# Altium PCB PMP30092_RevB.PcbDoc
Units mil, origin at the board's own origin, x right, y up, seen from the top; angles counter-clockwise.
Board outline 7537.5 x 2575 mil, 2 copper layers (Top Layer, Bottom Layer), stack 62 mil thick; 65 components, 37 nets, 152 pads, 61 vias.
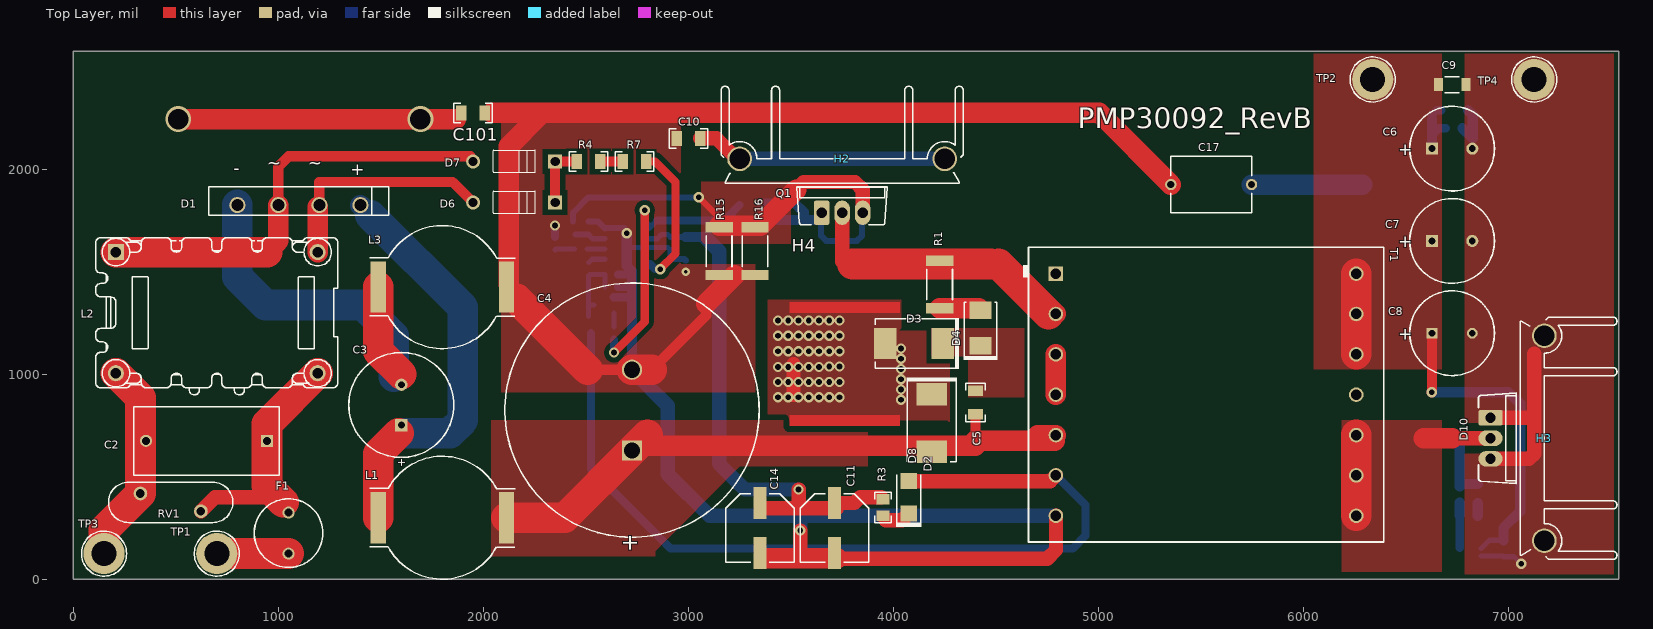
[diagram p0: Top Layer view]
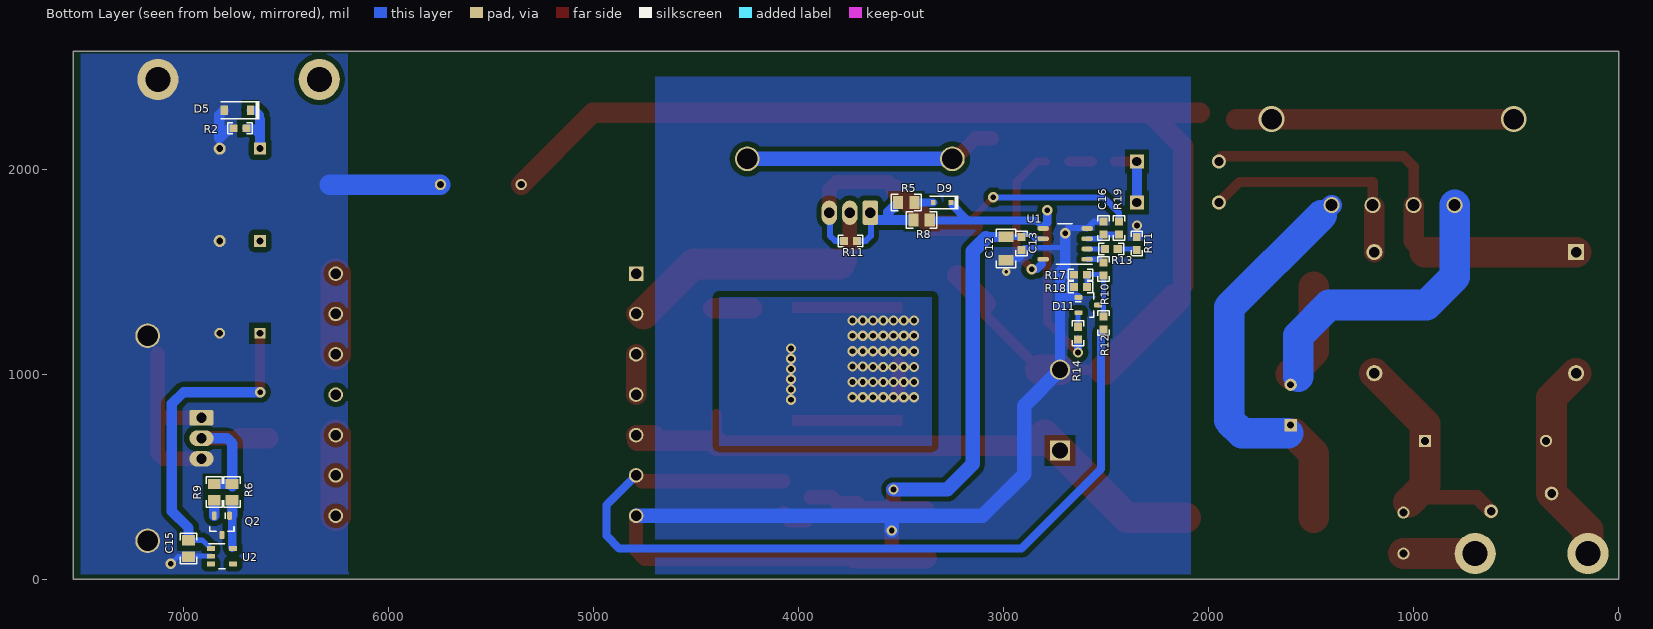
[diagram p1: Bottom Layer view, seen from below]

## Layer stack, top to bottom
Top Solder: solder mask 0.4, Solder Resist, Dk 3.5
Top Layer: signal copper 1.4
Dielectric1: core 59.2, FR-4, Dk 4.8
Bottom Layer: signal copper 1.4
Bottom Solder: solder mask 0.4, Solder Resist, Dk 3.5

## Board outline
0,0 7537.5,0 7537.5,2575 0,2575

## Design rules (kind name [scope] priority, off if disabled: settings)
AcuteAngle [All] p1: minimum=4.50000000000000E+0001 checktracksonly=FALSE
AssemblyTestPointUsage [All] p1: valid=2
Clearance Clearance_1 [InNet('NetD2_1') vs InNet('NetC4_1')] p1: gap=30
Clearance Clearance_Keepouts [((IsTrack Or IsArc) And Not InPoly) And IsFree and IsKeepOut vs ((IsTrack Or IsArc) And Not InPoly) And IsFree and IsKeepOut] p2: gap=0
Clearance Clearance_BoardEdge_MountingHoles [OnCopper and InComponentClass('Mounting Holes') vs IsKeepOut] p3: gap=20
Clearance Clearance_BoardEdge_Poly [OnCopper and InPoly vs IsKeepOut] p4: gap=25
Clearance Clearance_BoardEdge [OnCopper and Not InComponentClass('Logo') and not InComponentClass('FiducialMark') and not InRegion(1000,500,4000,800) and Not IsKeepout vs IsKeepOut] p5: gap=20
Clearance Clearance_Poly [InPolygon] p6: gap=25
Clearance [All] p7: gap=7.87
ComponentClearance ComponentClearance_MountingHoles_FiducialMarks [InComponentClass('Mounting Holes') vs InComponentClass('FiducialMark')] p1: gap=50 collisioncheckmode=3 verticalgap=10 showdistances=FALSE
ComponentClearance ComponentClearance_Shunt [InComponentClass('Header') vs InComponentClass('Shunt')] p2: gap=0 collisioncheckmode=3 verticalgap=0 showdistances=FALSE
ComponentClearance ComponentClearance_Logo [InComponentClass('Logo')] p3: gap=50 collisioncheckmode=3 verticalgap=10 showdistances=FALSE
ComponentClearance ComponentClearance_ScrewToNut [(HasFootprint('NY PMS 440 0025 PH')) vs (HasFootprint('Keystone_1902C'))] p4: gap=5 collisioncheckmode=3 verticalgap=10 showdistances=FALSE
ComponentClearance ComponentClearance_MountingHoles [InComponentClass('Mounting Holes')] p5: gap=250 collisioncheckmode=3 verticalgap=100000 showdistances=FALSE
ComponentClearance ComponentClearance_SmallPassives [HasFootprint('0201*') or HasFootprint('0402*') or HasFootprint('0508') or HasFootprint('0603*') or HasFootprint('0612') or HasFootprint('0805*') or HasFootprint('0815*') or HasFootprint('0830*') or HasFootprint('1206*') or HasFootprint('1210*') or HasFootprint('1808*') or HasFootprint('1812*') or HasFootprint('1825*') or HasFootprint('2010*') or HasFootprint('2220*') or HasFootprint('2225*') or HasFootprint('2512*') or HasFootprint('2728*') or HasFootprint('3518*') vs HasFootprint('0201*') or HasFootprint('0402*') or HasFootprint('0508') or HasFootprint('0603*') or HasFootprint('0612') or HasFootprint('0805*') or HasFootprint('0815*') or HasFootprint('0830*') or HasFootprint('1206*') or HasFootprint('1210*') or HasFootprint('1808*') or HasFootprint('1812*') or HasFootprint('1825*') or HasFootprint('2010*') or HasFootprint('2220*') or HasFootprint('2225*') or HasFootprint('2512*') or HasFootprint('2728*') or HasFootprint('3518*')] p6: gap=20 collisioncheckmode=3 verticalgap=10 showdistances=FALSE
ComponentClearance ComponentClearance_THtoSMT [IsThruComponent vs IsSMTComponent] p7: gap=20 collisioncheckmode=3 verticalgap=30 showdistances=FALSE
ComponentClearance ComponentClearance_THtoTH [IsThruComponent vs IsThruComponent] p8: gap=10 collisioncheckmode=3 verticalgap=30 showdistances=FALSE
ComponentClearance [All] p9: gap=10 collisioncheckmode=3 verticalgap=10 showdistances=FALSE
DiffPairsRouting [All] p1: maxlimit=100 minlimit=10 mostfreqgap=10 toplayer_minwidth=15 toplayer_maxwidth=15 toplayer_prefwidth=15 bottomlayer_minwidth=15 bottomlayer_maxwidth=15 bottomlayer_prefwidth=15 maxuncoupledlength=1000
FabricationTestPointUsage TestPointUsage [All] p1: valid=2 allowmultiple=FALSE
FabricationTestpoint Testpoint [All] p1: side=3 testpointundercomponent=TRUE minsize=40 maxsize=100 preferedsize=60 minholesize=0 maxholesize=40 preferedholesize=32 testpointgrid=1 allowsidetop=TRUE allowsidebottom=TRUE usegrid=TRUE gridtolerance=0.01
FanoutControl Fanout_LCC [IsLCC] p1: bgadir=Out bgaviamode=Centered fanoutstyle=Auto fanoutdirection=Alternating viagrid=1 // Fanout_LCC (Default Rule)
FanoutControl Fanout_BGA [IsBGA] p2: bgadir=Out bgaviamode=Centered fanoutstyle=Auto fanoutdirection=Alternating viagrid=1 // Fanout_BGA (Default Rule)
FanoutControl Fanout_Default [All] p4: bgadir=Out bgaviamode=Centered fanoutstyle=Auto fanoutdirection=Alternating viagrid=1 // Fanout_Default (Default Rule)
FanoutControl Fanout_Small [(CompPinCount < 5)] p5: bgadir=Out bgaviamode=Centered fanoutstyle=Auto fanoutdirection=OutThenIn viagrid=1 // Fanout_Small (Default Rule)
Height [All] p1: minheight=0 maxheight=2000 prefheight=500
HoleSize [All] p1: absolutevalues=TRUE maxlimit=251 minlimit=8 maxpercent=80.000 minpercent=20.000
MinimumAnnularRing MinimumAnnularRing_ThermalPadVias [IsVia and InAnyComponent] p1: minimumring=5.91
MinimumAnnularRing [All] p2: minimumring=9
MinimumSolderMaskSliver MinimumSolderMaskSliver_Logo [InComponentClass('Logo') vs InComponentClass('Logo')] p1: minsoldermaskwidth=0.7
MinimumSolderMaskSliver [All] p2: minsoldermaskwidth=3.94
PlaneConnect [All] p1: planeconnectstyle=Relief reliefexpansion=10 reliefentries=4 reliefconductorwidth=10 reliefairgap=10
PolygonConnect [All] p1: connectstyle=Direct reliefconductorwidth=10 reliefentries=4 polygonreliefangle="90 Angle" airgapwidth=10
RoutingVias ThermalPadVias [IsVia and InAnyComponent] p1: holewidth=7.87 width=19.68 viastyle="Through Hole" minholewidth=7.87 minwidth=19.68 maxholewidth=12.99 maxwidth=23.62
RoutingVias [All] p2: holewidth=16 width=34 viastyle="Through Hole" minholewidth=7.87 minwidth=26 maxholewidth=40 maxwidth=65
SilkToBoardRegionClearance [Not ((IsComment or IsDesignator) And (Hide <> 'False')) and not InRegion(1000,500,4000,800)] p1:
SilkToSilkClearance SilkToSilkClearance_Pb-FreeLogo [(HasFootprint('Pb-Free_Overlay_Medium') OR HasFootprint('Pb-Free_Overlay_Small')) vs (HasFootprint('Pb-Free_Overlay_Medium') OR HasFootprint('Pb-Free_Overlay_Small'))] p1: silktosilkclearance=0
SilkToSilkClearance [All] p2: silktosilkclearance=4
SilkToSolderMaskClearance SilkToComonentPadClearance [IsPad and InAnycomponent] p1: minsilkscreentomaskgap=5 clearancetoexposedcopper=TRUE
SilkToSolderMaskClearance "Silk to Solder Mask Opening" [All] p2: minsilkscreentomaskgap=4 clearancetoexposedcopper=FALSE
SolderMaskExpansion [All] p1: expansion=1.97
Width [All] p1: maxlimit=150 minlimit=6 preferedwidth=10 minimp=50.000000 maximp=50.000000 favimp=50.000000 checkconnectedcopper=TRUE
14 further rules are at their usual default settings.

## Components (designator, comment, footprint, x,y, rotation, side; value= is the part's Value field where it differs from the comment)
C2 "B32922C3334M" B32922_14.5mm 650,675 r180 top
C3 "UCY2G180MPD" CY_1250x2000 1600,850 r90 top
C4 "LGW2G271MELB35" LGW_3000x3500 2725,825 r90 top
C5 "12062A100JAT2A" 1206 4400,862.5 r90 top
C6 "UHW1V681MPD6" HW_1000x2000 6725,2100 r0 top
C7 "UHW1V681MPD6" HW_1000x2000 6725,1650 r0 top
C8 "UHW1V471MPD" HW_1000x1600 6725,1200 r0 top
C9 "C3216X7R1H105K160AB" 1206_180 6725,2412.5 r0 top
C10 "GRM31BR72J102KW01L" 1206 3000,2150 r180 top
C11 "EEE-FC1V330P" SM_RADIAL_E 3712.5,250 r270 top
C12 "C1206C105K3RACTU" 1206 2987.5,1612.5 r270 bottom
C13 "06035C104KAT2A" 0603 2912.5,1637.5 r270 bottom
C14 "Used in BOM report" SM_RADIAL_E 3350,250 r270 top
C15 "08055C104KAT2A" 0805_HV 6975,150 r270 bottom
C16 "06035A101FAT2A" 0603 2512.5,1712.5 r90 bottom
C17 "DE1E3KX332MN4AP01F" KX_1000x700 5550,1925 r180 top
C101 "GRM31BR72J102KW01L" 1206 1950,2275 r180 top
D1 "GBU606" GBU 1100,1825 r180 top
D2 "SMCJ85A" SMC 4187.5,762.5 r270 top
D3 "SMCJ100A" SMC 4100,1150 r180 top
D4 "MURS160T3G" SMB 4425,1225 r90 top
D5 "MMSZ5255B-7-F" SOD-123 6737.5,2287.5 r0 bottom
D6 "1N4007" DO-41 2150,1837.5 r180 top
D7 "1N4007" DO-41 2150,2037.5 r180 top
D8 "ES1B-13-F" SMA 4075,400 r90 top
D9 "BAS316,115" sod-323 3300,1837.5 r0 bottom
D10 "MBR20H150CTG" TO-220AB 6912.5,687.5 r270 top
D11 "BAV70-E3-08" SOT-23 2587.5,1337.5 r180 bottom
F1 "37213150001" FUSE_372 1050,225 r270 top
H2 "V6560X" ASMN_V6560X 3750,2050 r0 top
H3 "V6560X" ASMN_V6560X 7175,687.5 r270 top
H4 "573300D00010G" HEATSINK_573300D00010G 3762.5,1050 r90 top
L1 "DO5040H-473MLB" DO5040H 1800,300 r0 top
L2 "744825510" WE-CMB_XL 700,1300 r0 top
L3 "DO5040H-473MLB" DO5040H 1800,1425 r0 top
Q1 "IPP60R385CP" TO-220AB 3750,1787.5 r0 top
Q2 "TBD" SOT-23 6812.5,262.5 r270 bottom
R1 "CRCW25120000Z0EG" 2512 4225,1437.5 r90 top
R2 "RC0603FR-0720KL" 0603 6725,2200 r180 bottom
R3 "CRCW080510R0FKEA" 0805_HV 3950,350 r90 top
R4 "CRCW1206100KFKEA" 1206 2512.5,2037.5 r180 top
R5 "CRCW08050000Z0EA" 0805_HV 3475,1837.5 r0 bottom
R6 "CRCW08052K15FKEA" 0805_HV 6762.5,425 r270 bottom
R7 "CRCW1206100KFKEA" 1206 2737.5,2037.5 r180 top
R8 "CRCW080510R0FKEA" 0805_HV 3400,1751.57 r0 bottom
R9 "CRCW0805100RFKEA" 0805_HV 6850,425 r270 bottom
R10 "CRCW0603100RFKEA" 0603 2512.5,1512.5 r90 bottom
R11 "CRCW0603100KFKEA" 0603 3746.95,1650 r180 bottom
R12 "CRCW060321K5FKEA" 0603 2512.5,1250 r270 bottom
R13 "CRCW06030000Z0EA" 0603 2475,1610.81 r0 bottom
R14 "CRCW06033K92FKEA" 0603 2637.5,1200 r270 bottom
R15 "RLP73K3AR16FTDF" 2512 3150,1600 r90 top
R16 "Used in BOM report" 2512 3325,1600 r90 top
R17 "CRCW060337K4FKEA" 0603 2625,1485.81 r180 bottom
R18 "Used in BOM report" 0603 2625,1425 r180 bottom
R19 "CRCW06031K00FKEA" 0603 2437.5,1712.5 r270 bottom
RT1 "NCP18WM474J03RB" 0603 2350,1637.5 r270 bottom
RV1 "B72214S0271K101" VAR_B72214S0271 475,375 r0 top
T1 "750316326" Wurth_750316326 5525,900 r0 top
TP1 "Suggest using a net name here" Keystone1503-2 700,125 r0 top
TP2 "Suggest using a net name here" Keystone1503-2 6337.5,2437.5 r0 top
TP3 "Suggest using a net name here" Keystone1503-2 150,125 r0 top
TP4 "Suggest using a net name here" Keystone1503-2 7125,2437.5 r0 top
U1 "UCC28633DR" D0007A_N 2700,1635.81 r0 bottom
U2 "UCC24650DBVR" DBV0005A_N 6812.5,112.5 r180 bottom

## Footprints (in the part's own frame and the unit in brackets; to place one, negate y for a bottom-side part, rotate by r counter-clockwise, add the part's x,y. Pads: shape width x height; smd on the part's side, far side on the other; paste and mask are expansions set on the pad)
0603 [mm] "0603 from SM-752 data"
  rect 1x0.95 smd: 1(-0.8,0) 2(0.8,0)
  silkscreen extent -1.52,-0.69 1.52,0.69, body extent -0.87,-0.47 0.87,0.47, height 1
0805_HV [mil] "0805 with 30mil clearance between pads"
  rect 50x63 smd: 1(-40,0) 2(40,0)
  silkscreen extent -74,-40 74,40, body extent -43,-29 43,29, height 57
1206 [mm] "1206 from SM-752 data"
  rect 1.3x1.85 smd: 1(-1.45,0) 2(1.45,0)
  silkscreen extent -2.4,-1.21 2.4,1.21, body extent -1.7,-0.9 1.7,0.9, height 1.35
1206_180 [mm] "1206_180"
  rect 1.1x1.6 smd: 1(-1.7,0) 2(1.7,0)
  silkscreen extent -0.9,-1 0.9,1, body extent -1.75,-0.95 1.75,0.95, height 1.8
2512 [mm] "Chip Resistor, Body 6.3x3.2mm, IPC Medium Density"
  rect 1.3x3.4 smd: 1(-2.95,0) 2(2.95,0)
  silkscreen extent -1.9,-1.6 1.9,1.6, body extent -3.22,-1.67 3.22,1.67, height 0.71
ASMN_V6560X [mm] "TH, 2-Leads, Body 29x12mm, Pitch 25.4mm"
  round 3.05 hole 2.55: 1(-12.7,0) 2(12.7,0)
  silkscreen extent -15,-3 15,9, body extent -15,-3 15,9, height 37.5
B32922_14.5mm [mm] "Epcos film capacitors, 15mm spacing"
  rect 1.5x1.5 hole 1: 1(-7.5,0)
  round 1.5 hole 1: 2(7.5,0)
  silkscreen extent -9,-4.25 9,4.25, body extent -9,-4.25 9,4.25, height 14.5
CY_1250x2000 [mil] "Nichicon"
  rect 60x60 hole 33.46: 1(-98.43,0)
  round 60 hole 33.46: 2(98.43,0)
  silkscreen extent -256,-256 256,256, body extent -255,-255 255,256, height 847
D0007A_N [mm] "SOIC, 7-Leads, Body 4.9x3.9mm, Pitch 1.27mm, IPC Medium Density"
  oval 1.45x0.6 smd: 1(-2.725,1.905) 2(-2.725,0.635) 3(-2.725,-0.635) 4(-2.725,-1.905) 5(2.725,-1.905) 6(2.725,-0.635) 8(2.725,1.905)
  silkscreen extent -3.32,-2.5 1.1,2.52, body extent -3.01,-2.45 3.01,2.45, height 1.75
DBV0005A_N [mm] "SOT23, 5-Leads, Body 2.9x1.6mm, Pitch 0.95mm, Lead Span 2.8mm, IPC Medium Density"
  rrect17% 1x0.6 smd: 1(-1.375,0.95) 2(-1.375,0) 3(-1.375,-0.95) 4(1.375,-0.95) 5(1.375,0.95)
  silkscreen extent -1.63,-1.55 0.38,1.55, body extent -1.42,-1.46 1.42,1.46, height 1.09
DO5040H [mm] "Coilcraft recommended land pattern.  Document 479-2, rev 10/14/08"
  rect 1.9x6.35 smd: 1(-7.95,0) 2(7.95,0)
  silkscreen extent -9.01,-7.62 9,7.62, body extent -9.26,-7.55 9.28,7.55, height 12
DO-41 [mm] "diode"
  rect 1.75x1.75 hole 1.15: 1(-5.08,0)
  round 1.75 hole 1.15: 2(5.08,0)
  silkscreen extent -2.62,-1.37 2.59,1.35, body extent -5.51,-1.36 5.51,1.36, height 2.72
FUSE_372 [mm] "LITTELFUSE"
  round 1.5 hole 1: 1(-2.54,0) 2(2.54,0)
  silkscreen extent -4.25,-4.25 4.25,4.25, body extent -4.25,-4.25 4.25,4.25, height 8
GBU [mm] "Comchip / Diodes Inc diode bridge"
  round 2 hole 1.5: 1(-7.62,0) 2(-2.54,0) 3(2.54,0) 4(7.62,0)
  silkscreen extent -11.15,-2.28 11.15,1.28, body extent -11.15,-2.28 11.15,1.28, height 21.55
HEATSINK_573300D00010G [mil] "Aavid"
  Top Layer region: 248.03,-269.69 303.15,-269.69 303.15,269.68 248.03,269.68
  Top Layer region: -248.03,269.68 -303.15,269.68 -303.15,-269.69 -248.03,-269.69
  body extent -515,-250 515,250, height 400
HW_1000x1600 [mm] "TH, 2-Leads, Dia 10mm, Pin Spacing 5mm"
  rect 1.35x1.35 hole 0.85: 1(-2.5,0)
  round 1.35 hole 0.85: 2(2.5,0)
  silkscreen extent -5.25,-5.25 5.25,5.25, body extent -5.25,-5.25 5.26,5.25, height 17.51
HW_1000x2000 [mm] "TH, 2-Leads, 10.5x22mm, Pin Spacing 5mm"
  rrect7% 1.5x1.5 hole 0.85: 1(-2.5,0)
  round 1.5 hole 0.85: 2(2.5,0)
  silkscreen extent -5.25,-5.25 5.25,5.25, body extent -5.21,-5.24 5.24,5.24, height 22.01
Keystone1503-2 [mm] "Double Turret"
  round 5.1 hole 3.1: 1(0,0)
  silkscreen extent -2.79,-2.79 2.79,2.79, body extent -2.4,-2.4 2.38,2.4, height 9.22
KX_1000x700 [mm] "TH, 2-Leads, Dia 10mm, Lead Spacing 10mm"
  round 1.4 hole 0.9: 1(-5,0) 2(5,0)
  silkscreen extent -5,-3.5 5,3.5, body extent -5.32,-3.5 5.33,3.5, height 12.99
LGW_3000x3500 [mm] "TH, 2-Leads, Dia 30mm, Pin Spacing 10mm"
  rect 2.5x2.5 hole 2: 1(-5,0)
  round 2.5 hole 2: 2(5,0)
  silkscreen extent -15.75,-15.75 15.75,15.75, body extent -15.75,-15.75 15.76,15.75, height 37.01
SM_RADIAL_E [mm] "8 x 6.2mm:  Panasonic E"
  rect 4x1.6 smd: 1(-3.1,0) 2(3.1,0)
  silkscreen extent -4.25,-4.25 4.25,4.25, body extent -4.25,-4.25 4.25,4.25, height 6.5
SMA [mm] "Molded Diode, 2-Leads, Body 4.3x2.6mm, IPC Medium Density, based on OnSemi component dimensions and land pattern"
  rect 2x2 smd: 1(-2,0) 2(2,0)
  silkscreen extent -3.66,-1.57 2.79,1.57, body extent -2.6,-1.3 2.6,1.3, height 2.42
SMB [mil] "Molded Diode, 2-Leads, Body 5.4x3.6mm, IPC Medium Density, based on OnSemi component dimensions"
  rect 85x107.99 smd: 1(-87.01,0) 2(87.01,0)
  silkscreen extent -155,-82 125,82, body extent -106,-71 106,71, height 91
SMC [mil] "Molded Diode, 2-Leads, Body 6.9x5.8mm, IPC Medium Density, based on OnSemi component dimensions and land patterns"
  rect 110x150 smd: 1(-140.49,0) 2(140.49,0)
  silkscreen extent -221,-124 189,123, body extent -156,-116 156,116, height 91
SOD-123 [mm] "On Semi recommended land pattern"
  rect 0.915x1.22 smd: 1(-1.637,0) 2(1.637,0)
  silkscreen extent -2.74,-1.17 2.03,1.17, body extent -1.93,-0.9 1.93,0.9, height 1.35
sod-323 [mm] "NXP recommended land pattern"
  rect 0.6x0.6 smd paste-0.05: 1(-1.1,0) 2(1.1,0)
  silkscreen extent -2.06,-0.86 1.53,0.86, body extent -1.3,-0.67 1.3,0.68, height 1.1
SOT-23 [mm] "SOT23, 3-Leads, Body 2.9x1.3mm, Pitch 0.95mm, Lead Span 2.5mm, IPC Medium Density"
  rrect50% 1x0.6 smd: 1(-1.2,0.95) 2(-1.2,-0.95) 3(1.2,0)
  silkscreen extent -1.63,-1.5 0.7,1.5, body extent -1.16,-1.45 1.21,1.45, height 1
TO-220AB [mil] "Copied from Altium's version of TO3B"
  rrect25% 76x118.11 hole 50: 1(-100,0)
  oval 76x118.11 hole 50: 2(0,0) 3(100,0)
  silkscreen extent -221,-59 221,126, body extent -221,-59 221,126, height 765
VAR_B72214S0271 [mm] "EPCOS"
  round 1.7 hole 1.067: 1(-3.75,1.1) 2(3.75,-1.1)
  silkscreen extent -7.7,-2.5 7.7,2.5, body extent -7.74,-2.5 7.7,2.5, height 18.48
WE-CMB_XL [mm] "Wurth"
  rect 2x2 hole 1.3: 1(-12.5,7.5)
  round 2 hole 1.3: 6(12.5,7.5) 7(12.5,-7.5) 12(-12.5,-7.5)
  silkscreen extent -15,-10.18 15,9.3, body extent -15.25,-10.5 15.25,10.5, height 35
Wurth_750316326 [mm] "TH, 14-Leads, Body 44x36.5mm, Pitch 5mm"
  rect 1.8x1.8 hole 1.3: 1(-18.6,15)
  round 1.8 hole 1.3: 2(-18.6,10) 3(-18.6,5) 4(-18.6,0) 5(-18.6,-5) 6(-18.6,-10) 7(-18.6,-15) 8(18.6,-15) 9(18.6,-10) 10(18.6,-5) 11(18.6,0) 12(18.6,5) 13(18.6,10) 14(18.6,15)
  silkscreen extent -22.7,-18.25 22,18.25, body extent -22,-18.25 22,18.25, height 28.48

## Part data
C2: "CAP, Film, 0.33 µF, 630 V, +/- 20%, TH"
C3: library part UCY2G270MHD1TO, "CAP, AL, 27 µF, 400 V, +/- 20%, TH"
C4: "CAP, AL, 270 µF, 400 V, +/- 20%, TH"
C5: "CAP, CERM, 10 pF, 200 V, +/- 5%, C0G/NP0, 1206"
C6 C7: "CAP, AL, 680 µF, 35 V, +/- 20%, 0.019 ohm, TH"
C8: "CAP, AL, 470 µF, 35 V, +/- 20%, 0.03 ohm, TH"
C9: "CAP, CERM, 1 µF, 50 V, +/- 10%, X7R, 1206"
C10 C101: "CAP, CERM, 1000 pF, 630 V, +/- 10%, X7R, 1206"
C11: "CAP, AL, 33 µF, 35 V, +/- 20%, 0.4 ohm, SMD"
C12: "CAP, CERM, 1 µF, 25 V, +/- 10%, X7R, 1206"
C13: "CAP, CERM, 0.1 µF, 50 V, +/- 10%, X7R, 0603"
C14: library part Capacitor_Polarized, "CAP, [Technology], xxxF, xxV, +/-xx%, xxOhm ESR, [MountType]"
C15: "CAP, CERM, 0.1 µF, 50 V, +/- 10%, X7R, 0805"
C16: "CAP, CERM, 100 pF, 50 V, +/- 1%, C0G/NP0, 0603"
C17: "CAP, CERM, 3300 pF, 300 V, +/- 20%, E, D10xT7mm"
D1: "Diode, Switching-Bridge, 600 V, 6 A, TH"
D2: library part SMCJ75A, "Diode, TVS, Uni, 85 V, 1500 W, SMC"
D3: "Diode, TVS, Uni, 100 V, 1500 W, SMC"
D4: "Diode, Ultrafast, 600 V, 2 A, SMB"
D5: "Diode, Zener, 28 V, 500 mW, SOD-123"
D6 D7: "Diode, P-N, 1000 V, 1 A, TH"
D8: "Diode, Superfast Rectifier, 100 V, 1 A, SMA"
D9: "Diode, Ultrafast, 100 V, 0.25 A, SOD-323"
D10: "Diode, Schottky, 150 V, 10 A, TH"
D11: "Diode, Switching, 70 V, 0.25 A, AEC-Q101, SOT-23"
F1: "Fuse, 3.15 A, 250VAC/VDC, TH"
H2 H3: "HEATSINK, ALUM, ANOD, for TO-220"
H4: "Heatsink, DDPAK/TO-263, SMT"
L1 L3: "Inductor, Drum Core, Ferrite, 47 µH, 3.7 A, 0.05 ohm, SMD"
L2: "Coupled inductor, 10 mH, 5 A, 0.055 ohm, TH"
Q1: library part IPP60R199CP, "MOSFET, N-CH, 650 V, TO-220"
Q2: library part "MMBT5401LT1G, ON Semiconductor", "Transistor, PNP, 150 V, 0.5 A, SOT-23"
R1: "RES, 0, 5%, 1 W, AEC-Q200 Grade 0, 2512"
R2: "RES, 20.0 k, 1%, 0.1 W, 0603"
R3 R8: "RES, 10.0, 1%, 0.125 W, 0805"
R4 R7: "RES, 100 k, 1%, 0.25 W, 1206"
R5: "RES, 0, 5%, 0.125 W, 0805"
R6: "RES, 2.15 k, 1%, 0.125 W, 0805"
R9: "RES, 100, 1%, 0.125 W, 0805"
R10: "RES, 100, 1%, 0.1 W, 0603"
R11: "RES, 100 k, 1%, 0.1 W, 0603"
R12: "RES, 21.5 k, 1%, 0.1 W, 0603"
R13: "RES, 0, 5%, 0.1 W, 0603"
R14: "RES, 3.92 k, 1%, 0.1 W, 0603"
R15: library part CSRN2512FKR150, "RES, 0.16, 1%, 2 W, 2512"
R16 R18: library part Resistor, "RES, xxx ohm, x%, xW, [PackageReference]"
R17: "RES, 37.4 k, 1%, 0.1 W, 0603"
R19: "RES, 1.00 k, 1%, 0.1 W, 0603"
RT1: "Thermistor NTC, 470k ohm, 5%, 0603"
RV1: "Varistor, 430V, 4.5KA, TH"
T1: "Transformer, 250 uH, TH"
TP1 TP2 TP3 TP4: library part 1503-2, "Terminal, Turret, TH, Double"
U1: "High-Power Flyback Controller with Primary-Side Regulation and Peak-Power Mode, D0007A"
U2: "200-V Wake-Up Monitor for Fast Transient PSR, DBV0005A"

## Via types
v1: diameter 50, hole 28, Top Layer to Bottom Layer, 58 vias
v2: diameter 125.98, hole 100.39, Top Layer to Bottom Layer, 2 vias
v3: diameter 40, hole 18, Top Layer to Bottom Layer, 1 vias

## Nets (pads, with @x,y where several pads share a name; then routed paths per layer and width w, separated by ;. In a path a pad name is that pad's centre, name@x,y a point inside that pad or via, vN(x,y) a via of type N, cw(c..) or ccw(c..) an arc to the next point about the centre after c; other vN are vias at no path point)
GND: C6.2 C7.2 C8.2 C9.2 C15.2 C17.1 D5.2 D10.1 D10.3 H3.1 H3.2 Q2.3 R2.1 TP4.1 U2.2 | length 1892.7
  Top Layer w70: D10.3 7100,587.5 7125,612.5 7125,787.5 ; D10.1 7125,787.5 ; 7125,1100 7125,787.5
  Bottom Layer w25: U2.2 6972.5,112.5 C15.2 7027.5,110 v1(7062.5,75)
  Bottom Layer w50: R2.1@6775,2200 6825,2150 6825,2264.47 D5.2
  Bottom Layer w100: C17.1 6287.5,1925
NetC2_1: C2.1 F1.1 L2.7 RV1.2 | length 1135.3
  Top Layer w70: RV1.2 690.94,400 1000,400
  Top Layer w150: 945.28,454.72 C2.1 945.28,757.88 L2.7 ; 970.28,429.72 1025,375
NetC2_2: C2.2 L2.12 RV1.1 TP3.1 | length 1002.7
  Top Layer w150: TP3.1 150,240.94 RV1.1 327.36,885.23 L2.12
NetC3_1: C3.1 D1.1 L1.1 | length 2024.6
  Top Layer w150: L1.1 1487.01,612.01 1587.5,712.5
  Bottom Layer w100: D1.1 1450,1775
  Bottom Layer w150: 1450,1775 1900,1325 1900,775 1837.5,712.5 1612.5,712.5
NetC3_2: C3.2 D1.4 L3.1 | length 1903.4
  Top Layer w150: L3.1 1487.01,1112.99 1600,1000
  Bottom Layer w150: D1.4 800,1475 937.5,1337.5 1412.5,1337.5 1562.5,1187.5 1562.5,987.5
NetC4_1: C4.1 C5.1 D2.2 L1.2 T1.5 | length 3061.5
  Top Layer w50: 4400,675 C5.1
  Top Layer w100: 2800,650 4400,650 ; 4400,675 T1.5@4787.5,675 ; 4703.15,703.15 T1.5
  Top Layer w150: L1.2 2396.85,300 C4.1 2800,703.15
NetC5_2: C5.2 D3.1 D4.1
NetC6_1: C6.1 C7.1 C8.1 C9.1 C15.1 D5.1 R2.2 T1.12 T1.13 T1.14 TP2.1 U2.1 | length 2263.9
  Top Layer w50: v1(6625,912.5) 6626.57,914.07 C8.1
  Top Layer w150: T1.12 T1.13 T1.14
  Bottom Layer w25: U2.1 6906.73,190 C15.1
  Bottom Layer w40: 6626.57,2164.07 6662.5,2200 R2.2 ; 6626.57,2241.04 6626.57,2264.07 6650,2287.5 D5.1
  Bottom Layer w50: v1(6625,912.5) 7000,912.5 7056.89,855.61 7056.89,331.89 6975,250 C15.1 ; C6.1 6626.57,2164.07 6626.57,2241.04
NetC10_1: C10.1 H2.1 H2.2 | length 1221.8
  Top Layer w70: C10.1 3137.5,2150 H2.1@3237.5,2050
  Bottom Layer w70: H2.1 H2.2
NetC11_1: C11.1 C12.1 C13.1 C14.1 R3.2 U1.6 | length 2526.3
  Top Layer w70: C14.1@3375,347.05 3537.5,347.05 ; v1(3537.5,437.5) 3537.5,347.05 ; C11.1 3809.55,372.05 3837.5,400 R3.2@3940,400 ; C11.1@3725,350 3725,347.05 3537.5,347.05
  Bottom Layer w25: U1.6 2848.31,1660.81 2869,1681.5 C13.1@2900,1681.5
  Bottom Layer w30: C13.1@2913.09,1669.59 C12.1
  Bottom Layer w50: C12.1 3067.91,1669.59 3075,1662.5 3087.5,1662.5
  Bottom Layer w70: 3087.5,1662.5 3150,1600 3150,562.5 3275,437.5 v1(3537.5,437.5)
NetC16_1: C16.1 R19.2 U1.3 | length 151.1
  Bottom Layer w25: C16.1 2532.7,1660.81 U1.3
  Bottom Layer w30: R19.2@2450,1681 C16.1
NetC101_2: C101.2 | length 1352.9
  Top Layer w100: v2(511.81,2244.09) v2(1692.91,2244.09) 1864.67,2244.09
NetD1_2: D1.2 D6.2 L2.6 | length 1125.8
  Top Layer w50: D1.2 1200,1937.5 1850,1937.5 D6.2
  Top Layer w100: L2.6 D1.2@1192.12,1817.12
NetD1_3: D1.3 D7.2 L2.1 | length 2135.5
  Top Layer w50: D1.3 1000,2012.5 1050,2062.5 D7.2@1937.5,2062.5
  Top Layer w100: 945.28,1595.28 1000,1650 D1.3
  Top Layer w150: L2.1 945.28,1595.28
NetD2_1: D2.1 D3.2 | length 151
  Top Layer w70: 3512.99,899.02 3512.99,1050
  other v1: 4037.5,875 3437.5,887.5 3487.5,887.5 3537.5,887.5 3587.5,887.5 3637.5,887.5 3687.5,887.5 3737.5,887.5 4037.5,925 3437.5,962.5 3487.5,962.5 3537.5,962.5 3587.5,962.5 3637.5,962.5 3687.5,962.5 3737.5,962.5 4037.5,975 4037.5,1025 3437.5,1035.45 3487.5,1035.45 3537.5,1035.45 3587.5,1035.45 3637.5,1035.45 3687.5,1037.5 3737.5,1037.5 4037.5,1075 3437.5,1112.5 3487.5,1112.5 3537.5,1112.5 3587.5,1112.5 3637.5,1112.5 3687.5,1112.5 3737.5,1112.5 4037.5,1125 3437.5,1187.5 3487.5,1187.5 3537.5,1187.5 3587.5,1187.5 3637.5,1187.5 3687.5,1187.5 3737.5,1187.5 3437.5,1262.5 3487.5,1262.5 3537.5,1262.5 3587.5,1262.5 3637.5,1262.5 3687.5,1262.5 3737.5,1262.5
NetD4_2: D4.2 R1.1 | length 190.6
  Top Layer w100: R1.1 D4.2@4415.65,1321.36
NetD6_1: D6.1 D7.1 R4.2 | length 505.4
  Top Layer w50: D6.1 D7.1 R4.2
  Bottom Layer w50: D6.1 D7.1
NetD8_1: D8.1 R3.1 | length 126.8
  Top Layer w70: R3.1@3962.5,287.5 4042.24,287.5 D8.1
NetD9_1: D9.1 R8.1 R14.2 U1.5 | length 1566.6
  Top Layer w40: v1(2637.5,1106.25) 2787.5,1256.25 v1(2787.5,1800)
  Bottom Layer w25: U1.5 2846.48,1750
  Bottom Layer w40: v1(2637.5,1106.25) R14.2 ; v1(2787.5,1800) 2787.5,1737.5 2800,1725 ; 2846.48,1750 3187.5,1750 ; 3250,1825 3187.5,1762.5 3187.5,1750 ; R8.1@3358.43,1750 3187.5,1750
NetD9_2: D9.2 R5.1 | length 91.7
  Bottom Layer w40: D9.2 R5.1
NetD10_2: D10.2 R6.1 R9.1 T1.8 T1.9 T1.10 | length 1176.6
  Top Layer w70: 6725,687.5 D10.2
  Top Layer w100: 6587.5,687.5 6725,687.5
  Top Layer w150: T1.8 T1.9 T1.10
  Bottom Layer w50: R6.1@6762.5,452.5 R6.1 ; R9.1 R6.1 ; D10.2 6787.5,687.5 6762.5,662.5 R6.1
NetD11_2: D11.2 R14.1 | length 65.8
  Bottom Layer w25: R14.1 D11.2@2637.5,1297.34
NetD11_3: D11.3 R10.1 R12.1 R17.2 R18.2 | length 364.3
  Bottom Layer w25: R12.1 2512.5,1337.5 ; R10.1 2512.5,1337.5 ; R10.1@2517.3,1485.81 R17.2 R18.2 ; D11.3 2512.5,1337.5
NetF1_2: F1.2 TP1.1 | length 350
  Top Layer w150: TP1.1 F1.2
NetQ1_1: Q1.1 R5.2 R8.2 R11.2 | length 477.3
  Bottom Layer w30: Q1.1@3646.95,1784.45 3646.95,1675 3671.95,1650 R11.2
  Bottom Layer w50: R8.2 3562.5,1751.57 ; R5.2 3562.5,1790 3562.5,1751.57 ; Q1.1@3623.43,1751.57 3562.5,1751.57
NetQ1_2: Q1.2 R1.2 T1.2 | length 1281.2
  Top Layer w70: 3750,1550 Q1.2@3750,1775
  Top Layer w100: 4756.3,1293.7 T1.2
  Top Layer w150: 3800,1537.5 4475,1537.5 ; 4512.5,1537.5 4756.3,1293.7
NetQ1_3: Q1.3 R11.1 R15.2 R16.2 R19.1 | length 1979.2
  Top Layer w30: v1(3050,1862.5) 3150,1762.5 3150,1725 R15.2
  Top Layer w70: 3525,1900 3562.5,1937.5 3812.5,1937.5 3850,1900 Q1.3
  Top Layer w100: R15.2@3150,1725 3350,1725 3525,1900
  Bottom Layer w30: R19.1 2437.5,1787.5 2512.5,1862.5 v1(3050,1862.5) ; R11.1 3821.95,1650 3846.95,1675 Q1.3@3846.95,1784.45
NetQ2_1: Q2.1 R6.2 U2.5 | length 218.5
  Bottom Layer w40: U2.5@6762.5,154.04 6762.5,312.5
  Bottom Layer w50: 6762.5,312.5 R6.2@6762.5,372.5
NetQ2_2: Q2.2 R9.2 | length 62.7
  Bottom Layer w50: Q2.2 R9.2@6849.9,372.4
NetR4_1: R4.1 R7.2 | length 110.8
  Top Layer w50: R4.1 R7.2
NetR7_1: R7.1 U1.8 | length 700.8
  Top Layer w40: R7.1 2837.5,2037.5 2937.5,1937.5 2937.5,1587.5 v1(2862.5,1512.5)
  Bottom Layer w40: 2812.5,1537.5 2837.5,1512.5 v1(2862.5,1512.5)
NetR10_2: R10.2 U1.1 | length 87.2
  Bottom Layer w25: R10.2 2529.31,1560.81 U1.1
NetR13_1: R13.1 RT1.2 | length 95.5
  Bottom Layer w25: RT1.2 2354.8,1610.81 R13.1
NetR13_2: R13.2 U1.2 | length 86.2
  Bottom Layer w25: R13.2 U1.2
NetT1_3: T1.3 T1.4 | length 196.9
  Top Layer w100: T1.4 T1.3
PGND: C4.2 C10.2 C11.2 C12.2 C13.2 C14.2 C16.2 C17.2 C101.1 D11.1 L3.2 R15.1 R16.1 R17.1 R18.1 RT1.1 T1.7 U1.4 | length 11585.4
  Top Layer w50: 2508.66,1021.85 C4.2 ; 2821.85,1021.85 3087.5,1287.5 3087.5,1344.59
  Top Layer w70: 3545.18,102.95 v1(3545.18,237.5) ; C11.2@3725,102.95 3727.95,100 4750,100 4792.72,142.72 T1.7
  Top Layer w100: 2044.49,2275 5003.15,2275 C17.2 ; L3.2@2125,1437.01 2125,2112.5 2275,2262.5 ; 3087.5,1344.59 3226.77,1483.86 ; C14.2@3375,102.95 3545.18,102.95 C11.2@3725,102.95
  Top Layer w150: 2162.5,1368.01 2508.66,1021.85 ; C4.2 2821.85,1021.85
  Bottom Layer w25: 2706,1618.5 C13.2@2900,1618.5
  Bottom Layer w30: C16.2 2559.53,1744 U1.4 2594.41,1712.5 2687.5,1712.5 ; C13.2 2912.5,1575 2925,1562.5 2980.41,1562.5 C12.2
  Bottom Layer w40: RT1.1 v1(2350,1725) ; D11.1 2724.9,1374.9 ; R18.1 2725,1425 ; R17.1 2708.27,1485.81
  Bottom Layer w50: v1(2700,1687.5) 2700,1527.54 2725,1502.54 2725,1425 C4.2
  Bottom Layer w70: C4.2 2900,846.85 2900,512.5 3103.05,309.45 3537.5,309.45 ; v1(3545.18,237.5) 3545.18,301.77 3537.5,309.45 ; T1.7 3537.5,309.45
  other v3: 2987.5,1500
VBIAS: D8.2 R12.2 T1.6 | length 4344.3
  Top Layer w70: D8.2 4765.16,478.74 T1.6
  Bottom Layer w40: R12.2@2525,1200 2525,537.5 2912.5,150 4875,150 4937.5,212.5 4937.5,361.52 T1.6
pads on no net: T1.1 T1.11 U2.3 U2.4

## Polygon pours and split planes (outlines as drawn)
GND on Top Layer "Top Layer-No Net 7" (solid, pour order 24): 7112.5,350 7112.5,925 7512.5,925 7512.5,350
GND on Top Layer "Top Layer-No Net 6" (solid, pour order 20): 6787.5,612.5 7512.5,612.5 7512.5,25 6787.5,25
NetD10_2 on Top Layer "Top Layer-No Net 5" (solid, pour order 18): 6187.5,775 6675,775 6675,37.5 6187.5,37.5
GND on Top Layer "Top Layer-No Net 4" (solid, pour order 16): 6787.5,2562.5 6787.5,762.5 7512.5,762.5 7512.5,2562.5
NetC6_1 on Top Layer "Top Layer-No Net 3" (solid, pour order 14): 6050,1025 6675,1025 6675,2562.5 6050,2562.5
NetC4_1 on Top Layer "Top Layer-No Net 1" (solid, pour order 8): 2037.5,112.5 2837.5,112.5 2837.5,137.5 3250,550 3875,550 3875,775 2037.5,775
PGND on Top Layer "Top Layer-No Net 2" (solid, pour order 10): 2087.5,2300 2962.5,2300 2962.5,1537.5 3325,1537.5 3325,912.5 2087.5,912.5
NetQ1_3 on Top Layer "Top Layer-No Net 8" (solid, pour order 28): 3062.5,1937.5 3062.5,1650 3075,1637.5 3500,1637.5 3500,1937.5
NetD2_1 on Top Layer "Top Layer-No Net" (solid, pour order 32): 4037.5,1362.5 4037.5,1225 4025,1212.5 4275,1212.5 4275,762.5 4262.5,775 3387.5,775 3387.5,1362.5
NetC5_2 on Top Layer "Top Layer-No Net 9" (solid, pour order 34): 4187.5,1225 4637.5,1225 4637.5,887.5 4364.57,887.5 4364.57,1072.93 4362.5,1075 4350,1087.5 4187.5,1087.5
GND on Bottom Layer "Bottom Layer-No Net 1" (solid, pour order 26): 7500,25 6187.5,25 6200,37.5 6200,2562.5 7500,2562.5
PGND on Bottom Layer "Bottom Layer-No Net" (solid, pour order 12): 2087.5,2450 2087.5,25 4700,25 4700,2450
NetD2_1 on Bottom Layer "Bottom Layer-No Net 2" (solid, pour order 2): 3350,1375 4387.5,1375 4387.5,650 3350,650

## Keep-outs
Keep-Out Layer:
  text ".Layer_Name" at 577,-858.49 h60

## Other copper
Top Layer:
  text ".Layer_Name" at 577,-858.49 h60
Bottom Layer:
  text ".Layer_Name" at 577,-858.49 h60

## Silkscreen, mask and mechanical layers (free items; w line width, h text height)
Top Overlay:
  text "PMP30092_RevB" at 4900,2200 h100
  text ".Layer_Name" at 577,-858.49 h60
Bottom Overlay:
  text ".Layer_Name" at 577,-858.49 h60
Top Paste:
  text ".Layer_Name" at 577,-858.49 h60
Bottom Paste:
  text ".Layer_Name" at 577,-858.49 h60
Top Solder:
  text ".Layer_Name" at 577,-858.49 h60
  text ".Layer_Name" at 577,-858.49 h60
Bottom Solder:
  text ".Layer_Name" at 577,-858.49 h60
Drill Guide:
  text ".Layer_Name" at 577,-858.49 h60
M1 Board Outline:
  the board outline again, w10
  text ".Layer_Name" at 577,-858.49 h60
M2 Board Dimensions:
  rectangle: 125,-400 500,-275
  rectangle: 0,-275 125,-150
  lines w7: 0,-275 1000,-275 ; 125,-400 125,-150 ; 250,-400 250,-150 ; 500,-400 500,-150 ; 750,-400 750,-150 ; 0,-400 0,-150 1000,-150 1000,-400 0,-400
  text ".Layer_Name" at 577,-858.49 h60
M3 3D STEP Top:
  text ".Layer_Name" at 577,-858.49 h60
M4 3D STEP Bottom:
  text ".Layer_Name" at 577,-858.49 h60
M5 Assembly Top:
  lines w10: -292,-930.17 6308,-930.17 ; -292,-726.83 6310,-726.83 ; -292,-523.5 -292,-1133.5 3713,-1133.5 6310,-1133.5 6310,-523.5 -291.5,-523.5 -291.5,-1133.5 1284,-1133.5 ; 2173,-1133.5 2173,-523.5 ; 3440,-726.83 3440,-523.5 ; 4280,-726.83 4280,-523.5 ; 4902,-1140 4902,-937.17
  text "COMPONENTS MARKED 'DNP' SHOULD NOT BE POPULATED." at 1153.5,-318.5 h60
  text "ASSEMBLY VARIANT:" at 1153,-434 h60
  text ".VariantName" at 2189,-434 h60
  text "PCB VIEWED FROM TOP SIDE" at -228.5,-655.67 h60
  text "BOARD #:" at 2248,-655.67 h60
  text ".PRJ_Number" at 2793.5,-655.67 h60
  text "REV:" at 3638,-655.67 h60
  text ".PCB_Rev" at 3929.5,-655.67 h60
  text "SVN REV:" at 4476,-655.67 h60
  text ".VersionControl_RevNumber" at 4982,-655.67 h60
  text "TID #:" at 2248,-859 h60
  text ".TID" at 2793.5,-859 h60
  text "PLOT NAME =" at -228.5,-1064.34 h60
  text ".plot_File_Name" at 577,-1064.34 h60
  text "GENERATED    :" at 2250,-1064.34 h60
  text ".Print_Date" at 3119.5,-1064.34 h60
  text ".Print_Time" at 3848.5,-1064.34 h60
  text "TEXAS INSTRUMENTS" at 5113,-1064.34 h60
M6 Assembly Bottom:
  lines w10: -292.5,-727.33 6309.5,-727.33 ; -290.5,-930.67 6309.5,-930.67 ; 1115.5,-1140.5 1115.5,-937.67 ; 1737.5,-727.33 1737.5,-524 ; 2577.5,-727.33 2577.5,-524 ; 3844.5,-1134 3844.5,-524 ; 4733.5,-1134 6309,-1134 6309,-524 -292.5,-524 -292.5,-1134 2304.5,-1134 6309.5,-1134 6309.5,-524
  text "COMPONENTS MARKED 'DNP' SHOULD NOT BE POPULATED." at 6102,-318 h60
  text ".VariantName" at 5058,-434 h60
  text "ASSEMBLY VARIANT:" at 6097,-434 h60
  text ".VersionControl_RevNumber" at 1035.5,-656.17 h60
  text "SVN REV:" at 1541.5,-656.17 h60
  text ".PCB_Rev" at 2088,-656.17 h60
  text "REV:" at 2379.5,-656.17 h60
  text ".PRJ_Number" at 3224,-656.17 h60
  text "BOARD #:" at 3769.5,-656.17 h60
  text "PCB VIEWED FROM BOTTOM SIDE" at 6246,-656.17 h60
  text ".TID" at 3224,-859.5 h60
  text "TID #:" at 3769.5,-859.5 h60
  text "TEXAS INSTRUMENTS" at 904.5,-1064.84 h60
  text ".Print_Time" at 2169,-1064.84 h60
  text ".Print_Date" at 2898,-1064.84 h60
  text "GENERATED    :" at 3767.5,-1064.84 h60
  text ".plot_File_Name" at 5440.5,-1064.84 h60
  text "PLOT NAME =" at 6246,-1064.84 h60
M9 Title Sheet:
  drawing of 57 lines, arcs and shapes, not listed
  text "1" at 739.84,8036.5 h70
  text "2" at 3235.5,8036.5 h70
  text "3" at 5724.84,8036.5 h70
  text "4" at 8231.51,8036.5 h70
  text "5" at 10730.5,8036.5 h70
  text "6" at 13235.5,8036.5 h70
  text "A" at -416.5,6893.5 h70
  text "A" at 14383.5,6893.5 h70
  text "B" at -416.5,4513.5 h70
  text "B" at 14383.5,4513.5 h70
  text "C" at -416.5,2138.5 h70
  text "C" at 14383.5,2138.5 h70
  text "PROJECT TITLE:" at 11343.5,277.5 h45
  text ".PRJ_Title" at 11393.5,144.17 h70
  text "DESIGNED FOR:" at 11343.5,-23.5 h45
  text ".PRJ_Customer" at 11393.5,-163.5 h70
  text "D" at -416.5,-231.5 h70
  text "D" at 14383.5,-231.5 h70
  text "FILE NAME:" at 11343.5,-323.5 h45
  text ".PCB_File_Name_No_Path" at 11393.5,-443.5 h70
  text "Texas Instruments (TI) and/or its licensors do not warrant the accuracy or completeness of this specification" at 6374,-605.34 h45
  text "ENGINEER:" at 11343.5,-613.5 h45
  text "LAYOUT BY:" at 12848.5,-613.5 h45
  text "or any information contained therein. TI and/or its licensors do not warrant that this design will meet" at 6329.01,-718 h45
  text ".PRJ_Engineer" at 11393.5,-768.49 h70
  text ".PCB_Layout" at 12899,-768.49 h70
  text "the specifications, will be suitable for your application or fit for any particular purpose, or will operate in" at 6329.01,-830.67 h45
  text ".Layer_Name" at 577,-858.49 h60
  text "ALTIUM DESIGNER VERSION:" at 12848.5,-923.5 h45
  text "an implementation. TI and/or its licensors do not warrant that the design is production worthy. You should" at 6329.01,-943.33 h45
  text "completely validate and test your design implementation to confirm the system functionality for your application." at 6374,-1056 h45
  text ".print_Scale" at 11393.5,-1056.83 h70
  text ".Application_BuildNumber" at 12899,-1056.83 h70
  text "1" at 739.84,-1263.5 h70
  text "2" at 3235.5,-1263.5 h70
  text "3" at 5724.84,-1263.5 h70
  text "4" at 8231.51,-1263.5 h70
  text "5" at 10730.5,-1263.5 h70
  text "6" at 13235.5,-1263.5 h70
M10 Fab Notes:
  lines w20: 11299,6300 11299,890 14290,890 14290,6300
  text ".Layer_Name" at 577,-858.49 h60
M11 Gerber Information:
  lines w10: -292,-930.17 6308,-930.17 ; -292,-726.83 6310,-726.83 ; -292,-523.5 -292,-1133.5 3713,-1133.5 6310,-1133.5 6310,-523.5 -291.5,-523.5 -291.5,-1133.5 1284,-1133.5 ; 2173,-1133.5 2173,-523.5 ; 3440,-726.83 3440,-523.5 ; 4280,-726.83 4280,-523.5 ; 4902,-1140 4902,-937.17
  text "ALL ARTWORK VIEWED FROM TOP SIDE" at -228.5,-655.67 h60
  text "BOARD #:" at 2248,-655.67 h60
  text ".PRJ_Number" at 2793.5,-655.67 h60
  text "REV:" at 3638,-655.67 h60
  text ".PCB_Rev" at 3929.5,-655.67 h60
  text "SVN REV:" at 4476,-655.67 h60
  text ".VersionControl_RevNumber" at 4982,-655.67 h60
  text "LAYER NAME =" at -228.5,-858.49 h60
  text "TID #:" at 2248,-859 h60
  text ".TID" at 2793.5,-859 h60
  text "PLOT NAME =" at -228.5,-1064.34 h60
  text ".plot_File_Name" at 577,-1064.34 h60
  text "GENERATED    :" at 2250,-1064.34 h60
  text ".Print_Date" at 3119.5,-1064.34 h60
  text ".Print_Time" at 3848.5,-1064.34 h60
  text "TEXAS INSTRUMENTS" at 5113,-1064.34 h60
M12 Stackup:
  text ".Layer_Name" at 577,-858.49 h60
M13 Component Bodies Top:
  text ".Layer_Name" at 577,-858.49 h60
M14 Component Bodies Bottom:
  text ".Layer_Name" at 577,-858.49 h60
M15 Courtyards Top:
  text ".Layer_Name" at 577,-858.49 h60
M16 Courtyards Bottom:
  text ".Layer_Name" at 577,-858.49 h60
Drill Drawing:
  text ".Layer_Name" at 577,-858.49 h60

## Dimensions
0,0 to 7537.5,0 on M2 Board Dimensions
0,0 to 0,2575 on M2 Board Dimensions
0,-400 to 1000,-400 on M2 Board Dimensions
